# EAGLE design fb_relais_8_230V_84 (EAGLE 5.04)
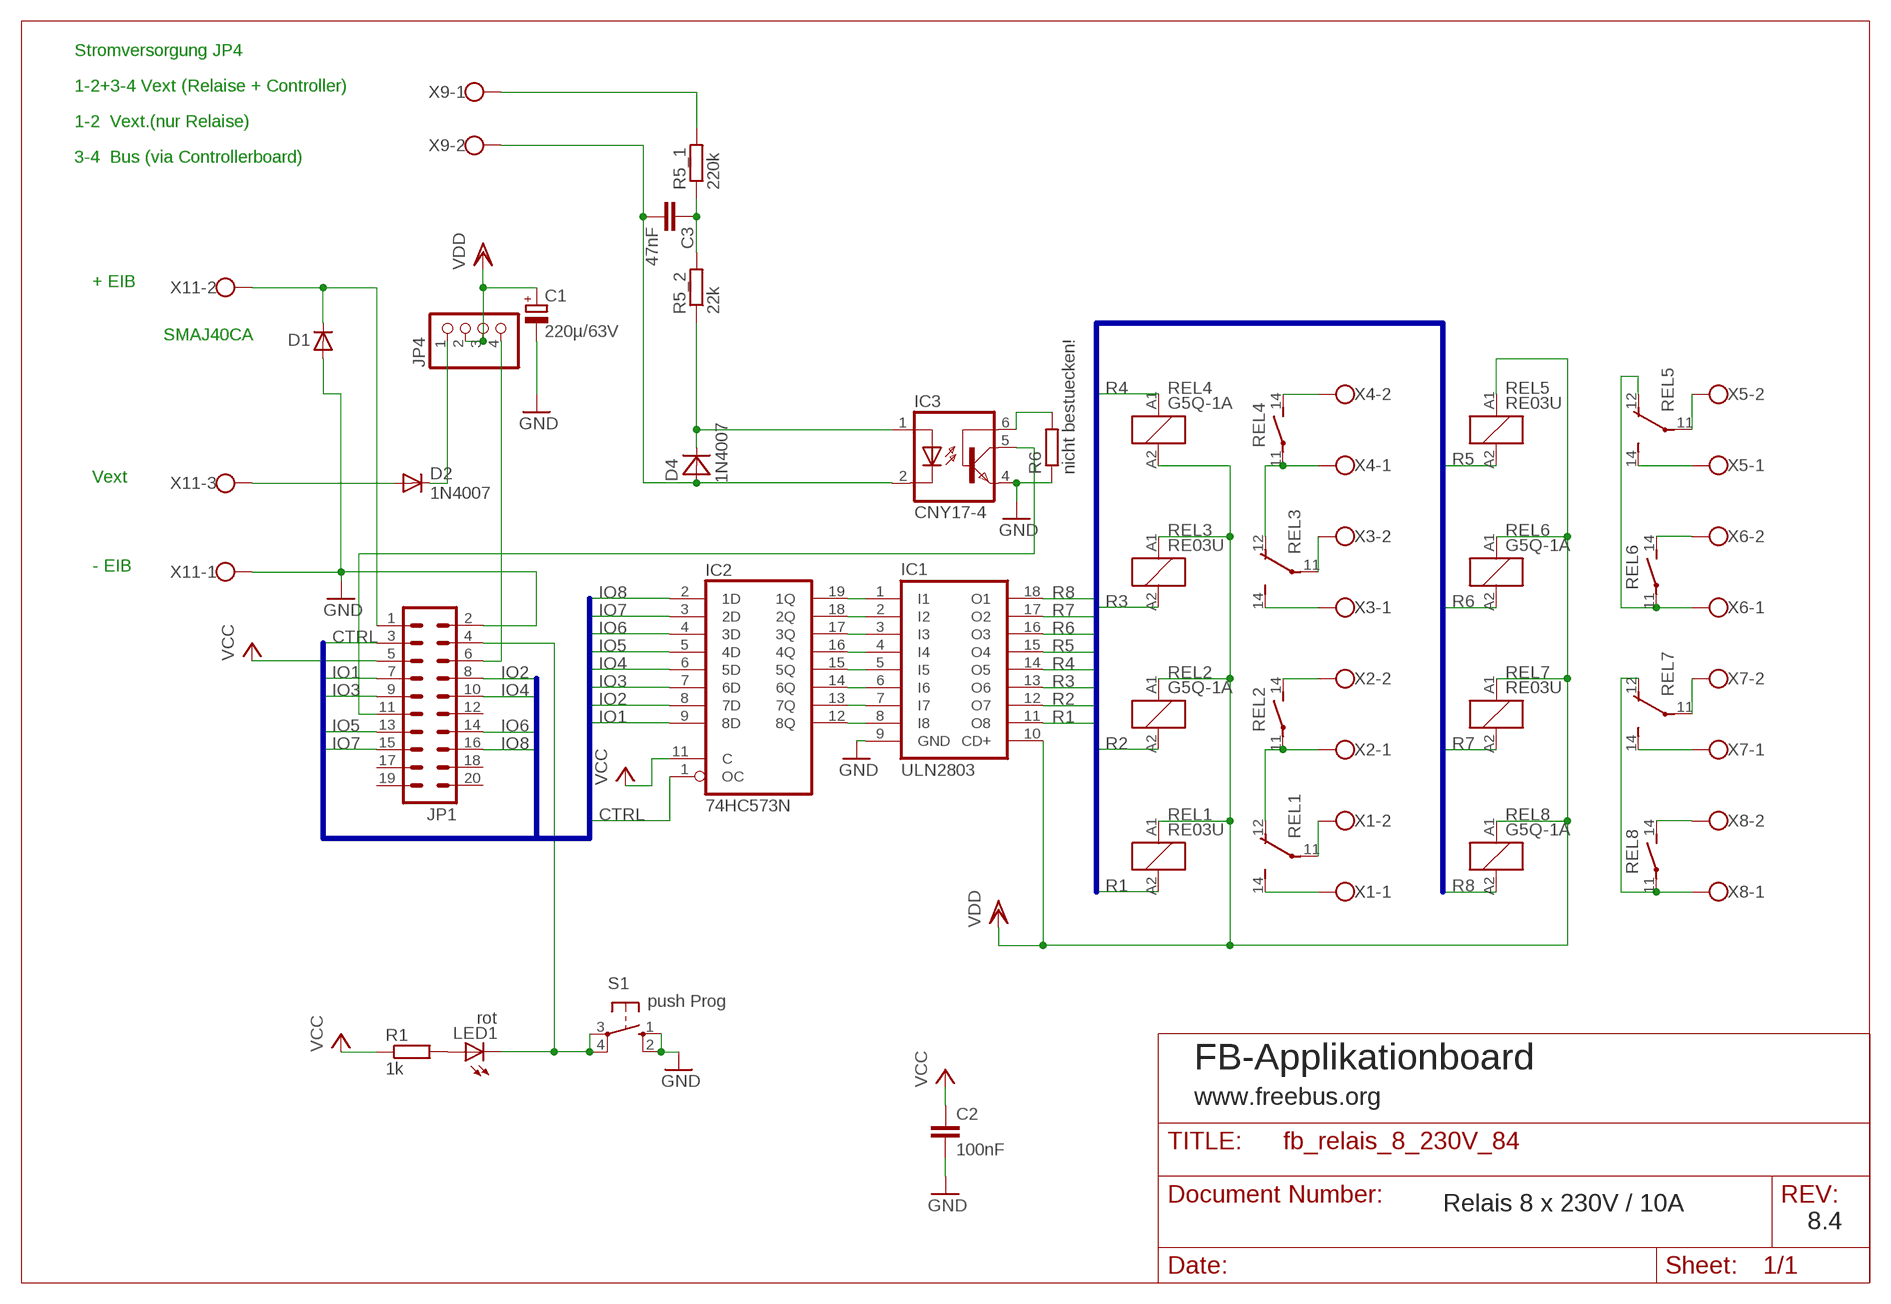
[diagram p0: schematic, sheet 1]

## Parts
C1  220µ/63V  CPOL-EUE5-10.5  [E5-10,5]
C2  100nF  C-EU050-024X044  [C050-024X044]
C3  47nF  C-EU025-025X050  [C025-025X050]
D1  D-SMB  [SMB]
D2  1N4007  1N4004  [DO41-10]
D4  1N4007  1N4007STEHEND  [RAD2,5]
IC1  ULN2803  ULN2803A  [DIL18]
IC2  74HC573N  [DIL20]
IC3  CNY17-4  CNY17  [DIL06]
JP1  ML20  [ML20]
JP4  PINHD-1X4  [1X04]
LED1  rot  LED3MM  [LED3MM]
R1  1k  R-EU_0207/2V  [0207/2V]
R5_1  220k  R-EU_0207/7  [0207/7]
R5_2  22k  R-EU_0207/2V  [0207/2V]
R6  nicht bestuecken!  R-EU_0207/2V  [0207/2V]
REL1  RE03U  [G5Q_1_EU]
REL2  G5Q-1A  RE030024  [RE-SCHRACK]
REL3  RE03U  [G5Q_1_EU]
REL4  G5Q-1A  RE030024  [RE-SCHRACK]
REL5  RE03U  [G5Q_1_EU]
REL6  G5Q-1A  RE030024  [RE-SCHRACK]
REL7  RE03U  [G5Q_1_EU]
REL8  G5Q-1A  RE030024  [RE-SCHRACK]
S1  push Prog  10-XX  [B3F-10XX]
X1  W237-102  [W237-102]
X2  W237-102  [W237-102]
X3  W237-102  [W237-102]
X4  W237-102  [W237-102]
X5  W237-102  [W237-102]
X6  W237-102  [W237-102]
X7  W237-102  [W237-102]
X8  W237-102  [W237-102]
X9  W237-102  [W237-102]
X11  W237-3E  [W237-3E]

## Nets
CTRL: IC2.1(OC) JP1.3
GND: C1.- C2.2 D1.2(A) IC1.9(GND) IC3.4(EMI) JP1.2 R6.1 S1.1(S) S1.2(S1) X11.1
IO1: IC2.9(8D) JP1.7
IO2: IC2.8(7D) JP1.8
IO3: IC2.7(6D) JP1.9
IO4: IC2.6(5D) JP1.10
IO5: IC2.5(4D) JP1.13
IO6: IC2.4(3D) JP1.14
IO7: IC2.3(2D) JP1.15
IO8: IC2.2(1D) JP1.16
N$1 [230Vac]: REL2.14(2:S) X2.2
N$2 [230Vac]: REL3.12(14:O) REL4.11(2:P) X4.1
N$3 [230Vac]: REL3.14(14:S) X3.1
N$4 [230Vac]: REL3.11(14:P) X3.2
N$5 [230Vac]: REL8.14(2:S) X8.2
N$6 [230Vac]: REL1.12(14:O) REL2.11(2:P) X2.1
N$7 [230Vac]: REL1.14(14:S) X1.1
N$8 [230Vac]: REL1.11(14:P) X1.2
N$9 [230Vac]: REL5.12(14:O) REL6.11(2:P) X6.1
N$10: REL5.14(14:S) X5.1
N$11 [230Vac]: REL7.11(14:P) X7.2
N$12 [230Vac]: REL6.14(2:S) X6.2
N$13 [230Vac]: REL5.11(14:P) X5.2
N$14: D2.A X11.3
N$15 [230Vac]: REL7.14(14:S) X7.1
N$16: R5_1.2 X9.1
N$17: D4.C IC3.1(A) R5_2.1
N$19: REL7.12(14:O) REL8.11(2:P) X8.1
N$20: D1.1(C) JP1.1 X11.2
N$25: D2.C JP4.1
N$27: JP1.4 LED1.K(C) S1.3(P) S1.4(P1)
N$28: LED1.A R1.2
N$29: JP1.6 JP4.4
N$30: IC1.1(I1) IC2.19(1Q)
N$31: IC1.2(I2) IC2.18(2Q)
N$32: IC1.3(I3) IC2.17(3Q)
N$33: IC1.4(I4) IC2.16(4Q)
N$34: IC1.5(I5) IC2.15(5Q)
N$36: IC1.6(I6) IC2.14(6Q)
N$37: IC1.7(I7) IC2.13(7Q)
N$38: IC1.8(I8) IC2.12(8Q)
N$39 [230Vac]: REL4.14(2:S) X4.2
N$40: IC3.6(BAS) R6.2
N$41: C3.2 D4.A IC3.2(C) X9.2
N$43: IC3.5(COL) JP1.11
N$45: C3.1 R5_1.1 R5_2.2
R1: IC1.11(O8) REL1.A2
R2: IC1.12(O7) REL2.A2
R3: IC1.13(O6) REL3.A2
R4: IC1.14(O5) REL4.A1
R5: IC1.15(O4) REL5.A2
R6: IC1.16(O3) REL6.A2
R7: IC1.17(O2) REL7.A2
R8: IC1.18(O1) REL8.A2
VCC: C2.1 IC2.11(C) JP1.5 R1.1
VDD: C1.+ IC1.10(CD+) JP4.2 JP4.3 REL1.A1 REL2.A1 REL3.A1 REL4.A2 REL5.A1 REL6.A1 REL7.A1 REL8.A1
Unconnected: JP1.12 JP1.17 JP1.18 JP1.19 JP1.20

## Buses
R[1..8]
IO[1..8],CTRL

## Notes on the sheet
- Stromversorgung JP4
- 1-2+3-4 Vext (Relaise + Controller)
- 1-2  Vext.(nur Relaise)
- 3-4  Bus (via Controllerboard)
- + EIB
- SMAJ40CA
- Vext
- - EIB
- FB-Applikationboard
- www.freebus.org
- Relais 8 x 230V / 10A
- 8.4

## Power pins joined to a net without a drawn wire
GND: IC2.10(GND)
VCC: IC2.20(VCC)

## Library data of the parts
C1 = rcl:CPOL-EU: POLARIZED CAPACITOR, European symbol
C2 C3 = rcl:C-EU: CAPACITOR, European symbol
D1 = semicon-smd-ipc:D-: DIODE
D2 = diode:1N4004: DIODE
D4 = diode:1N4007
IC1 = uln-udn:ULN2803A: DRIVER ARRAY
IC2 = 74xx-eu:74*573: 8-bit D latch BUS DRIVER
IC3 = optocoupler:CNY17: SIEMENS OPTO COUPLER
JP1 = con-harting-ml:ML20: HARTING
JP4 = pinhead:PINHD-1X4: PIN HEADER
LED1 = led:LED: LED
R1 R5_1 R5_2 R6 = rcl:R-EU_: RESISTOR, European symbol
REL1 REL3 REL5 REL7 = freebus_relay:RE03U
REL2 REL4 REL6 REL8 = relay:RE03*: Miniature PCB Relay 1 pole 6 A SCHRACK Source: http://www.schrack.com/.. 5812.pdf
S1 = switch-omron:10-XX: OMRON SWITCH
X1-X9 = con-wago-500:W237-102: WAGO SCREW CLAMP
X11 = con-wago-508:W237-3E: WAGO SREW CLAMP

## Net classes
1 230Vac: width 1.93 mm, clearance 5.08 mm to class 0, clearance 1.905 mm

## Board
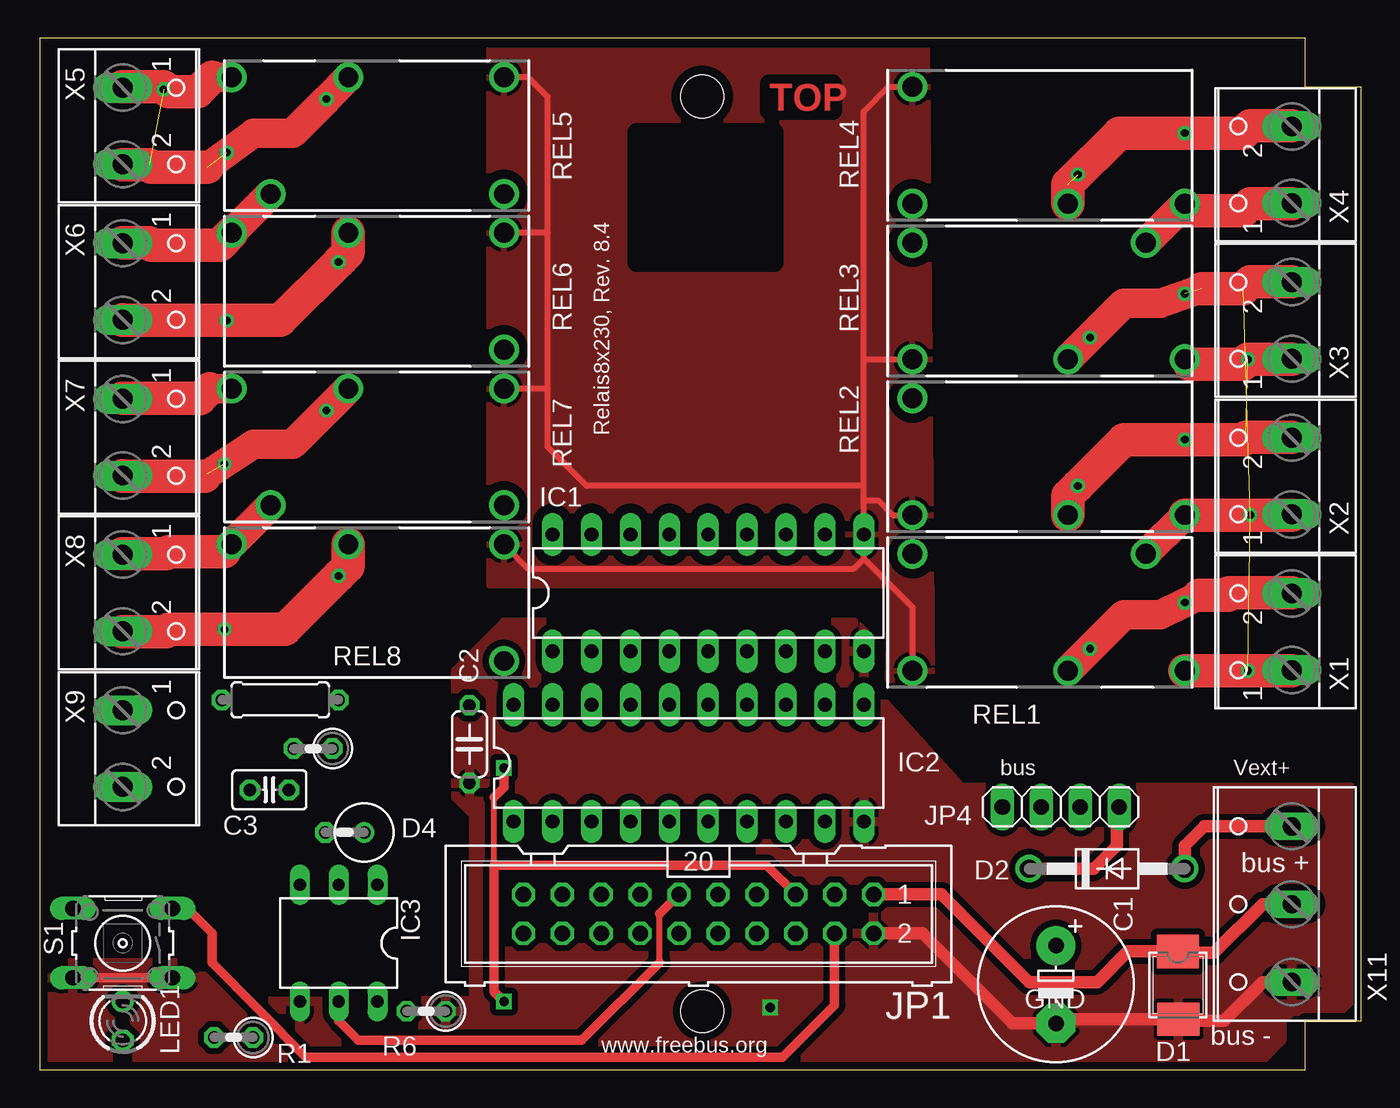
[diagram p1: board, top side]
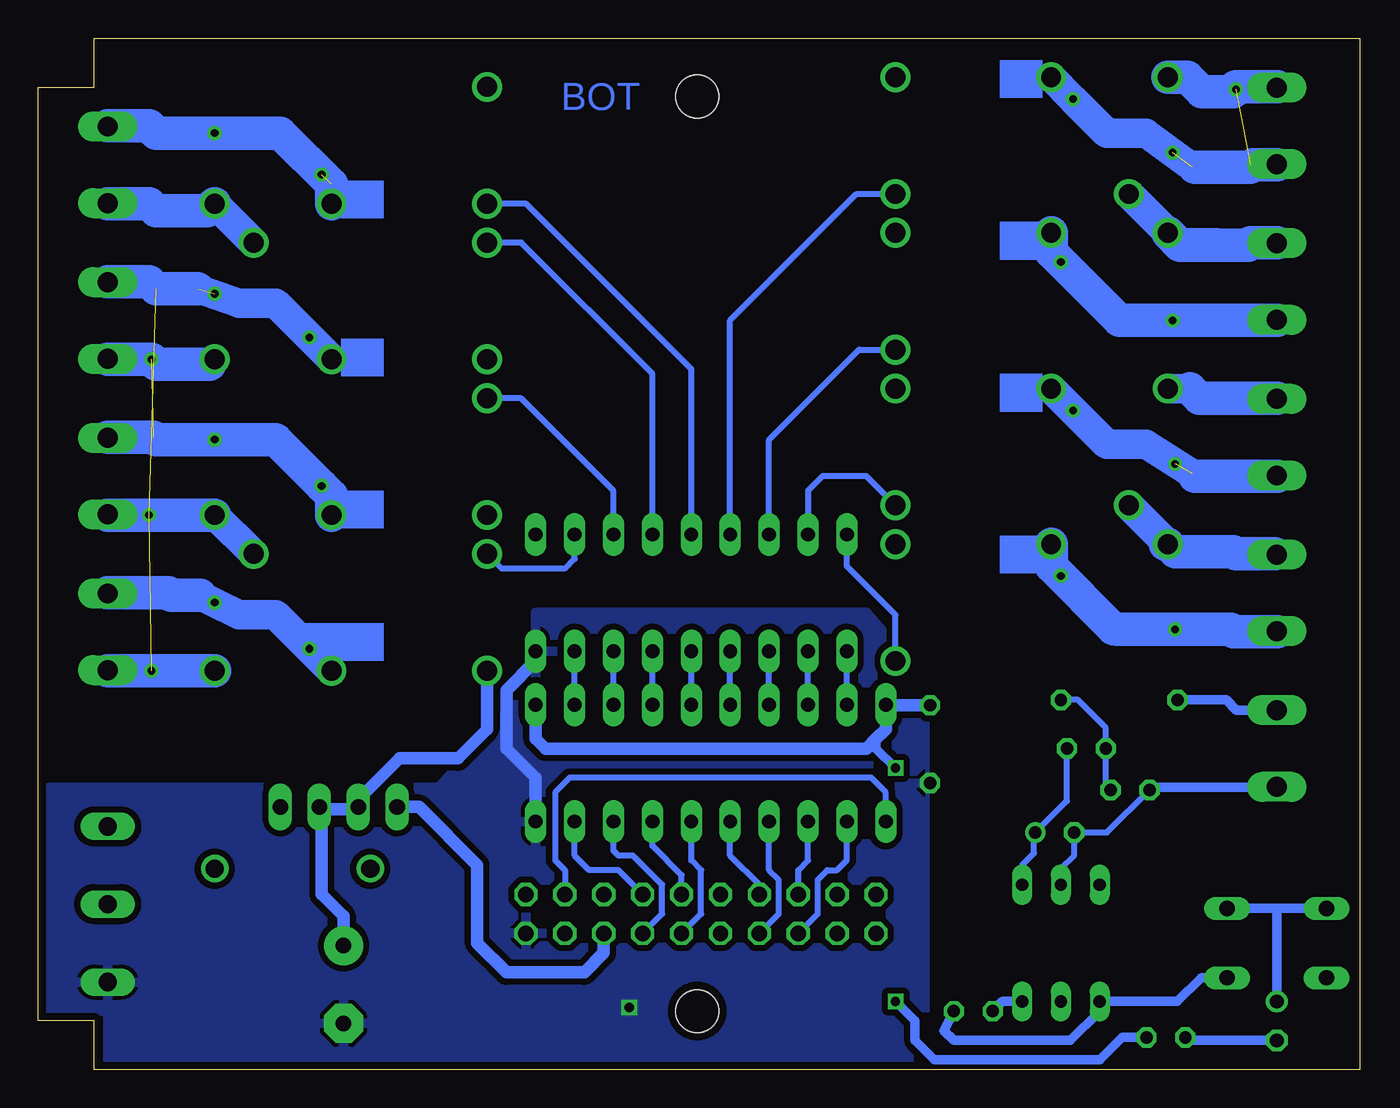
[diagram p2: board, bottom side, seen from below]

Size 86.28 x 67.31 mm. Coordinates in mm from the lower left corner, seen from the top.
Outline: 0,0.01 82.64,0 82.64,3.18 86.28,3.18 86.28,64.13 82.64,64.13 82.64,67.31 0,67.31 0,0.01
Copper layers (1*16): Top 0.035mm / dielectric 1.5mm / Bottom 0.035mm
Design rules "default": minimum track width 10mil, minimum drill 24mil, track to track 16mil, track to pad 12mil, pad to pad 16mil, via to via 16mil, smd to smd 8mil, copper to edge 20mil, drill to drill 10mil, minimum pad ring 10mil, minimum via ring 8mil, stop-mask expansion 4mil, vias tented up to drill 0mil, thermal gap 10mil
Holes 2.8 mm at 43.27,3.81 43.27,63.5
tKeepout: area 40.5,54.2 to 45.5,59.2
tRestrict: area 39,52.7 to 48,61.2

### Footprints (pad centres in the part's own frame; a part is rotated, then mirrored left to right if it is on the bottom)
E5-10,5 = drill 1.016 pad 2.54 round: + -2.54,0 | drill 1.016 pad 2.54 octagon: - 2.54,0
C050-024X044 = drill 0.813 octagon: 1 -2.54,0; 2 2.54,0
C025-025X050 = drill 0.813 octagon: 1 -1.27,0; 2 1.27,0
SMB = smd 2.159 x 2.743: 1 -2.311,-0.127; 2 2.108,-0.102
DO41-10 = drill 1.2 round: A 5.08,0; C -5.08,0
RAD2,5 = drill 0.813 octagon: A 1.27,0 | drill 0.813 round: C -1.27,0
DIL18 = drill 0.9 long: 1 -10.16,-3.81; 2 -7.62,-3.81; 3 -5.08,-3.81; 4 -2.54,-3.81; 5 0,-3.81; 6 2.54,-3.81; 7 5.08,-3.81; 8 7.62,-3.81; 9 10.16,-3.81; 10 10.16,3.81; 11 7.62,3.81; 12 5.08,3.81; 13 2.54,3.81; 14 0,3.81; 15 -2.54,3.81; 16 -5.08,3.81; 17 -7.62,3.81; 18 -10.16,3.81
DIL20 = drill 0.9 long: 1 -11.43,-3.81; 2 -8.89,-3.81; 3 -6.35,-3.81; 4 -3.81,-3.81; 5 -1.27,-3.81; 6 1.27,-3.81; 7 3.81,-3.81; 8 6.35,-3.81; 9 8.89,-3.81; 10 11.43,-3.81; 11 11.43,3.81; 12 8.89,3.81; 13 6.35,3.81; 14 3.81,3.81; 15 1.27,3.81; 16 -1.27,3.81; 17 -3.81,3.81; 18 -6.35,3.81; 19 -8.89,3.81; 20 -11.43,3.81
DIL06 = drill 0.813 long: 1 -2.54,-3.81; 2 0,-3.81; 3 2.54,-3.81; 4 2.54,3.81; 5 0,3.81; 6 -2.54,3.81
ML20 = drill 1 octagon: 1 -11.43,-1.27; 2 -11.43,1.27; 3 -8.89,-1.27; 4 -8.89,1.27; 5 -6.35,-1.27; 6 -6.35,1.27; 7 -3.81,-1.27; 8 -3.81,1.27; 9 -1.27,-1.27; 10 -1.27,1.27; 11 1.27,-1.27; 12 1.27,1.27; 13 3.81,-1.27; 14 3.81,1.27; 15 6.35,-1.27; 16 6.35,1.27; 17 8.89,-1.27; 18 8.89,1.27; 19 11.43,-1.27; 20 11.43,1.27
1X04 = drill 1.016 long: 1 -3.81,0; 2 -1.27,0; 3 1.27,0; 4 3.81,0
LED3MM = drill 0.9 octagon: A -1.27,0 | drill 0.9 round: K 1.27,0
0207/2V = drill 0.813 octagon: 1 -1.27,0; 2 1.27,0
0207/7 = drill 0.813 octagon: 1 -3.81,0; 2 3.81,0
G5Q_1_EU = drill 1.3 round: 11 1.27,-3.81; 12 6.35,3.81; 14 8.89,-3.81; A1 -8.89,-3.81; A2 -8.89,3.81
RE-SCHRACK = drill 1.3 round: 11 8.89,-3.81; 14 1.27,-3.81; A1 -8.89,-3.81; A2 -8.89,3.81
B3F-10XX = drill 1 long: 1 -3.251,2.261; 2 3.251,2.261; 3 -3.251,-2.261; 4 3.251,-2.261
W237-102 = drill 1.3 long: 1 -2.5,-1.27; 2 2.5,-1.27
W237-3E = drill 1.194 long: 1 -5.08,-0.635; 2 0,-0.635; 3 5.08,-0.635

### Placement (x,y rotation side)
C1  66.35,5.56 270 top
C2  28.06,21.24 270 top
C3  15,18.26 180 top
D1  74.45,5.4 270 top
D2  69.69,13.11 0 top
D4  19.92,15.48 180 top
IC1  43.65,31.12 0 top
IC2  42.38,20 0 top
IC3  19.52,8.26 180 top
JP1  43.02,10.16 180 top
JP4  66.67,17.14 180 top
LED1  5.42,3.17 90 top
R1  12.66,2.1 180 top
R5_1  15.71,24.13 180 top
R5_2  17.85,20.96 180 top
R6  25.23,3.81 180 top
REL1  65.88,29.85 0 top
REL2  65.88,40 0 top
REL3  65.88,50.16 0 top
REL4  65.88,60.32 0 top
REL5  21.42,60.96 180 top
REL6  21.42,50.8 180 top
REL7  21.42,40.64 180 top
REL8  21.42,30.48 180 top
S1  5.42,8.26 180 top
X1  80.48,28.58 90 top
X2  80.48,38.73 90 top
X3  80.48,48.89 90 top
X4  80.48,59.05 90 top
X5  6.69,61.59 270 top
X6  6.69,51.43 270 top
X7  6.69,41.27 270 top
X8  6.69,31.12 270 top
X9  6.69,20.96 270 top
X11  81.11,10.79 90 top

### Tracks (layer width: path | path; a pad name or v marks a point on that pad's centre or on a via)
CTRL
  Bottom 0.406: IC2.1 30.95,18.1 31.9,19.05 51.59,19.05 52.54,18.1 52.54,13.65 51.91,13.02 JP1.3
GND  (via drill 0.6)
  Top 0.61: S1.2 S1.1
  Top 0.813: X11.1 79.84,5.71 77.3,3.17 74.46,3.17 D1.2 66.62,3.29 C1.- | 66.03,3.02 63.49,3.02 57.62,8.89 JP1.2
  Bottom 0.61: S1.1 10.35,5.99 11.9,4.45 IC3.4 16.98,3.81 18.88,1.91 26.5,1.91 27.14,2.54 R6.1
  Bottom 0.813: C1.- 66.03,3.02 | IC1.9 53.81,26.67 55.71,24.77 55.71,20.96 53.81,19.05 IC2.10
  other vias: 47.7,4.05
  pour Top: 0.47,6.98 11.27,6.98 14.44,4.45 28.33,4.52 28.33,16.59 27.14,17.78 27.14,26.04 30.31,29.21 53.17,29.21 53.81,28.58 53.81,25.4 60.16,18.42 85.56,18.42 85.56,4.45 84.92,3.81 81.75,3.81 81.11,3.17 81.11,1.91 79.84,0.64 0.47,0.64
  pour Bottom: 28.41,0.64 81.75,0.64 81.75,3.81 85.56,3.81 85.56,18.42 60.16,18.42 53.81,25.4 53.81,29.85 32.22,29.85 28.41,25.4
IO1
  Bottom 0.406: JP1.7 48.41,13.02 50.32,13.02 51.27,13.97 IC2.9
IO2
  Bottom 0.406: JP1.8 45.55,10.16 45.55,12.06 47.46,13.97 48.41,13.97 48.73,14.29 IC2.8
IO3
  Bottom 0.406: JP1.9 44.28,12.7 46.19,14.61 IC2.7
IO4
  Bottom 0.406: JP1.10 43.02,10.16 43.02,13.02 43.65,13.65 IC2.6
IO5
  Bottom 0.406: JP1.13 39.2,12.06 41.11,13.97 IC2.5
IO6
  Bottom 0.406: JP1.14 37.94,10.16 37.94,12.38 38.57,13.02 IC2.4
IO7
  Bottom 0.406: JP1.15 36.66,13.02 36.03,13.65 IC2.3
IO8
  Bottom 0.406: JP1.16 35.39,10.16 35.39,12.38 34.76,13.02 34.12,13.02 33.49,13.65 IC2.2
N$1  (via drill 0.5)  (1 unrouted)
  Top 1.93: 81.75,41.27 X2.2
  Top 2.184: REL2.14 67.14,37.46 v67.78,38.1 70.8,41.12 v74.77,41.12 78.58,41.12 78.73,41.27 81.75,41.27
  Bottom 1.93: 77.46,41.12 77.5,41.09 | X2.2 81.75,41.27
  Bottom 2.184: REL2.14 67.14,37.46 v67.78,38.1 70.8,41.12 v74.77,41.12 77.46,41.12 | 77.62,41.12 78.58,41.12 78.73,41.27 81.75,41.27
  other vias: 78.89,46.35
N$2
  Top 1.93: REL3.12 REL4.11 75.24,56.04 | 77.56,56.04 77.62,56.04 | 81.75,56.52 X4.1
  Top 2.184: 75.24,56.04 77.56,56.04 78.58,56.04 79.05,56.52 81.75,56.52
  Bottom 1.93: REL3.12 REL4.11
  Bottom 2.184: REL4.11 75.24,56.04 78.58,56.04 79.05,56.52 81.75,56.52
N$3  (1 unrouted)
  Top 1.93: 75.08,46.04 REL3.14 | 81.75,46.35 X3.1
  Top 2.184: 78.58,46.04 78.89,46.35 81.75,46.35 | 75.08,46.04 78.42,46.04
  Bottom 1.93: REL3.14 75.08,46.04
  Bottom 2.184: 75.08,46.04 78.58,46.04 78.89,46.35 81.75,46.35
N$4  (via drill 0.5)  (3 unrouted)
  Top 1.93: REL3.11 v68.57,47.78 70.8,50.01 73.18,50.01 75.88,50.96 | 81.75,51.43 X3.2
  Top 2.184: 75.88,50.96 78.58,50.96 79.05,51.43 81.75,51.43
  Bottom 1.93: REL3.11 v68.57,47.78 70.8,50.01 73.18,50.01 75.88,50.96
  Bottom 2.184: 75.88,50.96 78.58,50.96 79.05,51.43 81.75,51.43
  other vias: 74.77,50.64 79.05,36.2 78.89,26.04
N$5  (via drill 0.5)
  Top 1.93: 5.39,28.58 X8.2
  Top 2.184: REL8.14 20.15,32.86 v19.52,32.23 16.03,28.73 v12.06,28.73 8.41,28.73 8.25,28.58 5.39,28.58
  Bottom 1.93: 5.39,28.58 X8.2
  Bottom 2.184: 16.08,28.79 20.15,32.86 REL8.14 | 9.36,28.73 8.41,28.73 8.25,28.58 5.39,28.58
N$6
  Top 1.93: REL1.12 REL2.11 | X2.1 81.75,36.2 | 78.58,36.2 78.73,36.2
  Top 2.184: REL2.11 77.61,36.2 | 77.61,36.2 77.62,36.2 | 77.61,36.2 78.58,36.2 | 78.73,36.2 81.75,36.2
  Bottom 1.93: REL1.12 REL2.11 | 81.75,36.2 X2.1
  Bottom 2.184: REL2.11 81.75,36.2
N$7
  Top 1.93: 77.56,26.04 77.62,26.04 | 81.75,26.04 X1.1
  Top 2.184: REL1.14 77.56,26.04 81.75,26.04
  Bottom 2.184: REL1.14 81.75,26.04
N$8  (via drill 0.5)
  Top 1.93: REL1.11 v68.57,27.46 70.8,29.69 73.02,29.69 | X1.2 81.75,31.12 | 75.72,30.96 v74.77,30.48 73.18,29.69 | 77.56,31.02 77.62,30.96
  Top 2.184: 81.75,31.12 77.64,31.12 | 75.72,30.96 77.62,30.96
  Bottom 1.93: REL1.11 v68.57,27.46 70.8,29.69 73.18,29.69 v74.77,30.48 75.72,30.96 | 81.75,31.12 X1.2
  Bottom 2.184: 75.72,30.96 77.62,30.96 77.78,31.12 81.75,31.12
N$9  (1 unrouted)
  Top 1.93: REL5.12 REL6.11 11.9,53.98 | 5.39,53.98 5.39,53.97 X6.1 | 9.36,53.82 9.36,53.85
  Top 2.184: 9.33,53.82 7.3,53.82 7.14,53.98 5.39,53.98 | 9.36,53.82 11.74,53.82 REL6.11
  Bottom 1.93: REL6.11 REL5.12 | 9.36,53.92 9.36,53.98 11.58,53.98 11.74,53.82
  Bottom 2.184: 5.39,53.98 7.14,53.98 7.3,53.82 11.74,53.82 REL6.11
N$10
  Top 1.93: 11.27,64.77 REL5.14 | 5.39,64.14 X5.1
  Top 2.184: 11.27,64.77 10.31,63.82 8.41,63.82 8.09,64.14 5.39,64.14
  Bottom 2.184: 5.39,64.14 8.09,64.14 8.25,63.98 8.25,63.82 10.31,63.82 11.27,64.77 REL5.14
N$11  (via drill 0.5)  (2 unrouted)
  Top 1.93: REL7.11 v18.73,43.02 16.5,40.8 13.96,40.8 10.79,38.73 | 9.36,38.73 9.36,38.75 | 5.39,38.74 5.39,38.73
  Top 2.184: 10.79,38.73 9.36,38.73 5.39,38.73 | X7.2 5.39,38.74
  Bottom 1.93: REL7.11 v18.73,43.02 16.5,40.8 13.96,40.8 10.95,38.89 10.79,38.73 | 9.36,38.73 9.36,38.75
  Bottom 2.184: 10.79,38.73 9.36,38.73 5.39,38.73
  other vias: 12.06,39.53
N$12  (via drill 0.5)
  Top 1.93: 9.38,48.89 9.36,48.89 | 5.39,48.9 5.39,48.89
  Top 2.184: REL6.14 20.15,53.34 v19.52,52.7 15.71,48.89 v12.22,48.89 9.38,48.89 5.39,48.89 | X6.2 5.39,48.9
  Bottom 2.184: REL6.14 20.15,53.34 15.71,48.89 v12.22,48.89 5.39,48.89
N$13  (via drill 0.5)  (2 unrouted)
  Top 1.93: REL5.11 v18.73,63.34 16.5,61.12 13.96,61.12 10.95,58.9 | 5.39,59.05 5.39,59.06 X5.2
  Top 2.184: 10.95,58.9 7.3,58.9 7.14,59.05 5.39,59.05
  Bottom 1.93: 10.79,58.88 10.94,58.88 | REL5.11 v18.73,63.34 16.5,61.12 13.96,61.12 10.95,58.9 10.79,58.9 10.79,58.88 | 10.79,58.88 10.78,58.9
  Bottom 2.184: 10.78,58.9 9.38,58.9 7.14,58.9 6.98,59.05 5.39,59.05
  other vias: 12.22,59.85 8.09,63.98
N$14
  Top 0.813: X11.3 76.03,15.88 74.77,14.61 D2.A
N$15
  Top 1.93: REL7.14 11.11,44.45 | 9.37,43.81 9.36,43.81 | 5.39,43.81 X7.1
  Top 2.184: 10.44,43.78 10.41,43.81 10.31,43.81 | 10.31,43.81 9.37,43.81 5.39,43.81 | 10.31,43.81 10.47,43.81 11.11,44.45
  Bottom 1.93: 11.11,44.45 REL7.14 | 5.39,43.81 X7.1
  Bottom 2.184: 11.11,44.45 10.47,43.81 5.39,43.81
N$16
  Bottom 0.61: X9.1 8.05,23.46 8.73,24.13 R5_1.2
N$17
  Bottom 0.406: R5_2.1 19.12,17.54 D4.C 21.27,15.4 21.27,14.13 22.06,13.33 IC3.1
N$19
  Top 1.93: 12.06,33.81 REL7.12 | 5.39,33.66 5.39,33.65 X8.1
  Top 2.184: 12.06,33.81 8.41,33.81 8.25,33.66 5.39,33.66
  Bottom 1.93: REL7.12 REL8.11
  Bottom 2.184: 5.55,33.66 8.09,33.66 8.25,33.81 12.06,33.81 | 12.06,33.81 12.03,33.78 | 12.06,33.81 REL8.11 12.69,34.29
N$20
  Top 0.813: X11.2 79.84,10.79 76.67,7.62 74.41,7.62 D1.1 71.04,7.71 69.05,5.71 64.61,5.71 58.89,11.43 JP1.1
N$24
  Bottom 2.184: 9.52,28.73 15.87,28.73
N$25
  Top 0.813: D2.C 68.83,13.11 70.32,14.61 70.32,16.99 JP4.1
N$27
  Top 0.61: S1.3 9.64,10.52 11.27,8.89 11.27,6.98 17.38,0.79 48.49,0.79 51.91,4.21 JP1.4
  Bottom 0.61: 5.55,10.52 S1.4 | 5.55,10.52 S1.3 | LED1.K 5.42,10.39 5.55,10.52
N$28
  Bottom 0.61: LED1.A 11.2,1.91 R1.2
N$29
  Bottom 0.813: JP4.4 61.43,17.15 57.62,13.33 57.62,8.26 55.71,6.35 50.63,6.35 49.37,7.62 JP1.6
N$30
  Bottom 0.406: IC2.19 IC1.1
N$31
  Bottom 0.406: IC2.18 IC1.2
N$32
  Bottom 0.406: IC2.17 IC1.3
N$33
  Bottom 0.406: IC2.16 IC1.4
N$34
  Bottom 0.406: IC2.15 IC1.5
N$36
  Bottom 0.406: IC2.14 IC1.6
N$37
  Bottom 0.406: IC2.13 IC1.7
N$38
  Bottom 0.406: IC2.12 IC1.8
N$39  (via drill 0.5)  (1 unrouted)
  Top 1.93: 81.75,61.59 X4.2
  Top 2.184: REL4.14 67.14,57.78 70.48,61.12 v74.77,61.12 78.58,61.12 79.05,61.59 81.75,61.59
  Bottom 1.93: X4.2 81.75,61.59
  Bottom 2.184: REL4.14 67.14,57.78 70.48,61.12 v74.77,61.12 77.48,61.12 | 77.62,61.12 78.58,61.12 79.05,61.59 81.75,61.59
  other vias: 67.78,58.42
N$40
  Bottom 0.61: IC3.6 23.33,4.45 R6.2
N$41
  Bottom 0.406: IC3.2 19.52,13.1 18.65,13.97 D4.A 16.5,15.48 C3.2
  Bottom 0.61: C3.2 13.25,18.42 5.46,18.42 X9.2
N$43
  Top 0.406: 40.48,6.98 40.48,10.16
  Top 0.61: IC3.5 19.52,3.17 20.79,1.91 35.39,1.91 40.48,6.98 | 40.48,10.16 JP1.11
N$45
  Bottom 0.406: R5_1.1 18.41,24.13 16.58,22.3 R5_2.2 16.58,18.65 C3.1
R1
  Bottom 0.406: REL1.A2 56.03,32.7 51.91,32.7 51.27,33.34 IC1.11
R2
  Bottom 0.406: IC1.12 48.73,37.78 54.76,43.81 REL2.A2
R3
  Bottom 0.406: IC1.13 46.19,45.4 54.76,53.98 REL3.A2
R4
  Bottom 0.406: IC1.14 43.65,45.72 54.45,56.52 REL4.A1
R5
  Bottom 0.406: IC1.15 41.11,48.89 32.85,57.15 REL5.A2
R6
  Bottom 0.406: IC1.16 38.57,41.12 32.7,46.99 REL6.A2
R7
  Bottom 0.406: IC1.17 36.03,37.78 35.08,38.73 32.22,38.73 REL7.A2
R8
  Bottom 0.406: REL8.A2 30.31,29.69 33.49,32.86 IC1.18
VCC  (via drill 0.6)
  Top 0.406: 29.68,13.33 29.68,17.78
  Top 0.61: v30.31,4.45 29.68,5.08 29.68,13.33 47.46,13.33 JP1.5 | 29.68,17.78 30.31,18.42 v30.31,19.69
  Bottom 0.61: R1.1 15.52,2.09 16.98,0.64 27.77,0.64 29.04,1.91 29.04,3.17 v30.31,4.45 | v30.31,19.69 31.58,20.96 31.58,21.59
  Bottom 0.813: C2.1 30.92,23.78 IC2.20 30.95,22.23 31.58,21.59 32.22,20.96 53.17,20.96 53.81,21.59 IC2.11
VDD
  Top 0.406: REL5.A1 31.9,64.77 33.17,63.5 33.17,54.61 | 33.17,54.61 REL6.A1 | 33.17,44.45 33.17,54.61 | 33.17,44.45 REL7.A1 | REL8.A1 31.9,32.7 53.17,32.7 53.81,33.34 | 53.81,33.34 IC1.10 53.81,37.15 | REL1.A1 56.98,30.16 53.81,33.34 | 53.81,37.15 53.81,38.1 | 53.81,38.1 53.81,46.35 | 53.81,46.35 53.81,62.55 55.4,64.14 REL4.A2 | REL2.A1 55.71,36.2 54.76,37.15 53.81,37.15 | 53.81,46.35 REL3.A1 | 33.17,44.45 33.17,40.64 35.71,38.1 53.81,38.1
  Bottom 0.813: C1.+ 66.35,10 67.78,11.43 67.78,16.99 | 67.78,16.99 JP4.2 | 67.78,16.99 65.56,16.99 JP4.3 65.4,17.62 62.7,20.32 58.89,20.32 56.98,22.23 REL1.A1
  pour Top (isolate 0.61): 29.36,66.68 57.94,66.68 58.25,25.4 55.4,25.4 55.56,31.59 29.36,31.59
(copper drawn outside any net)
  shapes: Bottom area x10

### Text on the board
Top: TOP
Bottom: BOT
tPlace: bus | Vext+ | bus + | bus -
tNames: REL4 | Relais8x230, Rev. 8.4 | GND | www.freebus.org
Document: A5 | A4 | A6 | A3 | A7 | A2 | A8 | A1 | EIB + | Vext+ | EIB - | Vext-
Drill_legend: Bohrlegende | Datum: 10.01.2009 22:11:37 | 2.8000 mm / 110.236 mil | 1.6000 mm / 62.992 mil | 1.3000 mm / 51.181 mil | 1.2000 mm / 47.244 mil | 1.1000 mm / 43.307 mil | 1.0000 mm / 39.370 mil | 0.9000 mm / 35.433 mil | 0.5000 mm / 19.685 mil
